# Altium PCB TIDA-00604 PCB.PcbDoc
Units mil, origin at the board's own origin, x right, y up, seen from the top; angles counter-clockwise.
Board outline 3890 x 2960 mil, 4 copper layers (Top Layer, Top, Mid-Layer 1, ly2, Mid-Layer 2, ly3, Bottom Layer, Bottom), stack 18.2 mil thick; 80 components, 35 nets, 214 pads, 61 vias.
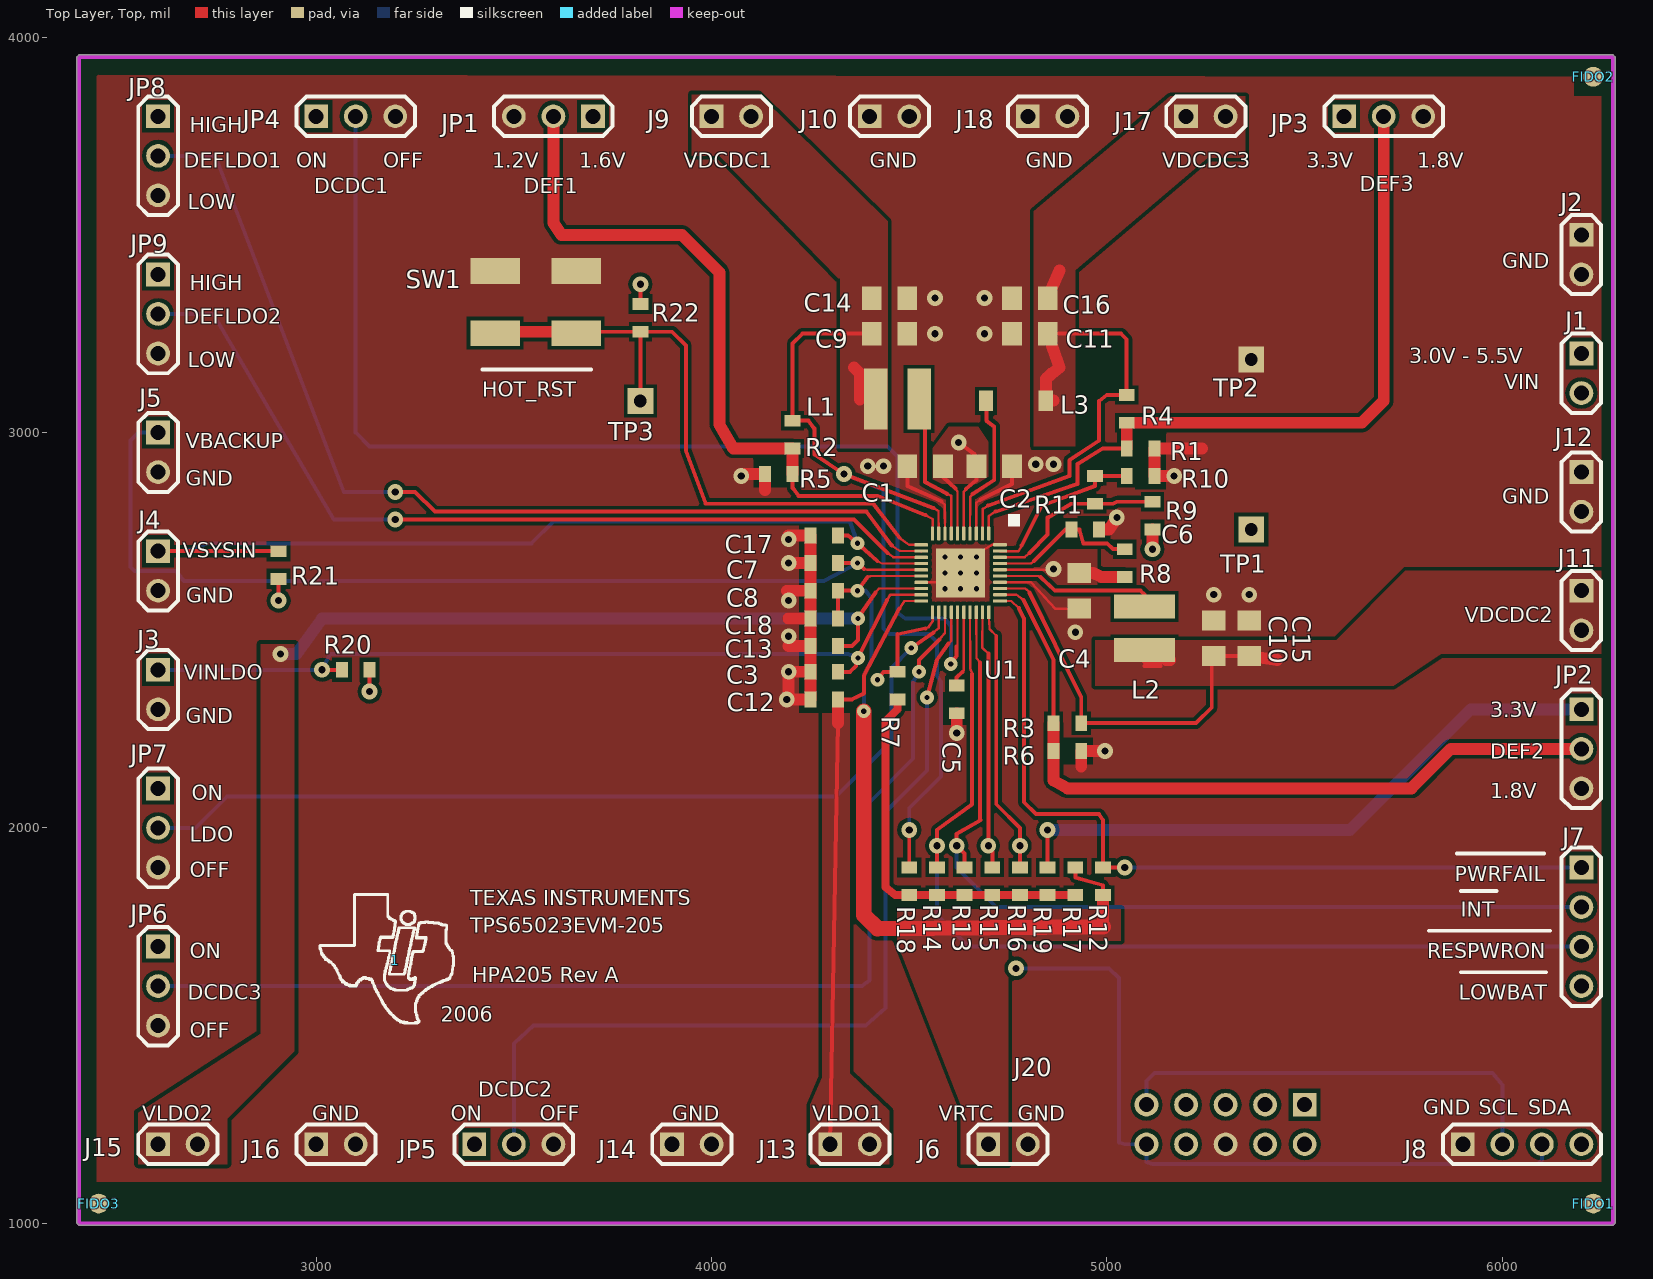
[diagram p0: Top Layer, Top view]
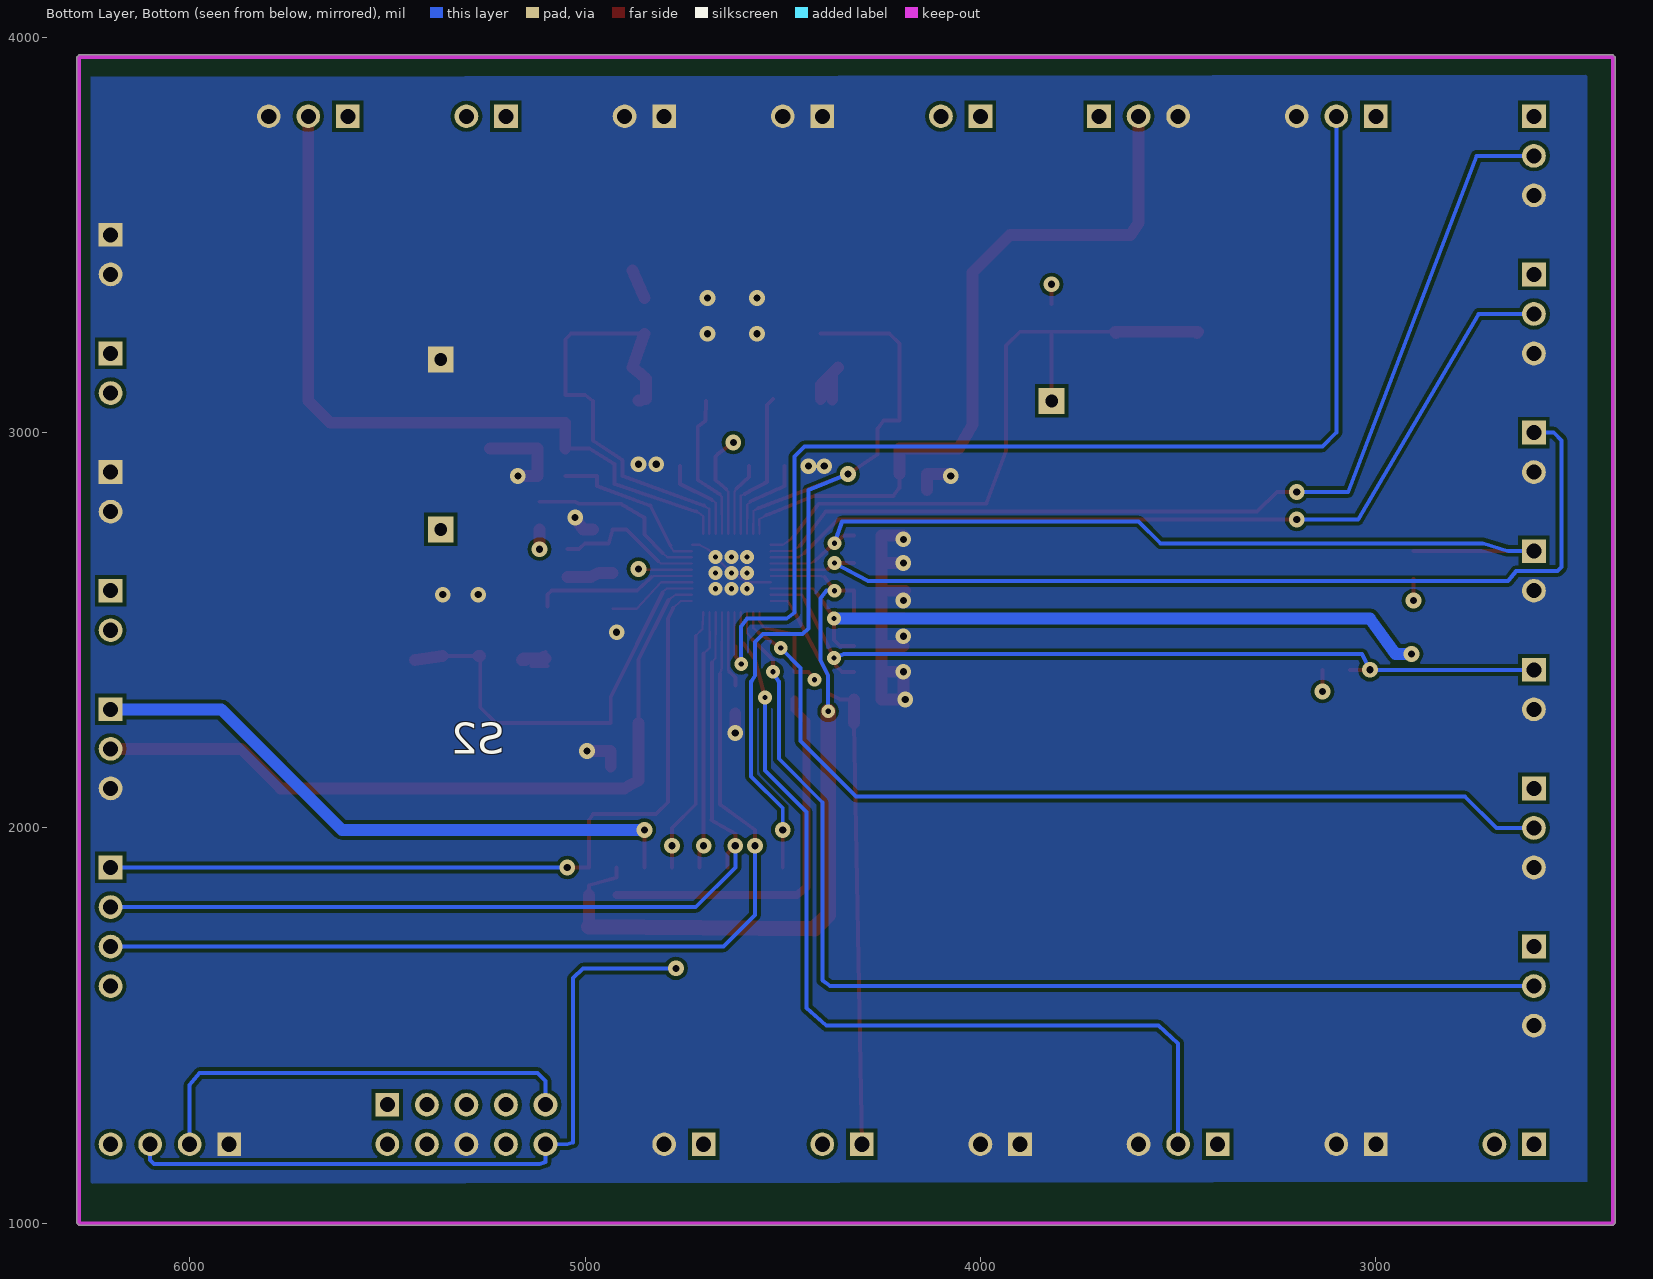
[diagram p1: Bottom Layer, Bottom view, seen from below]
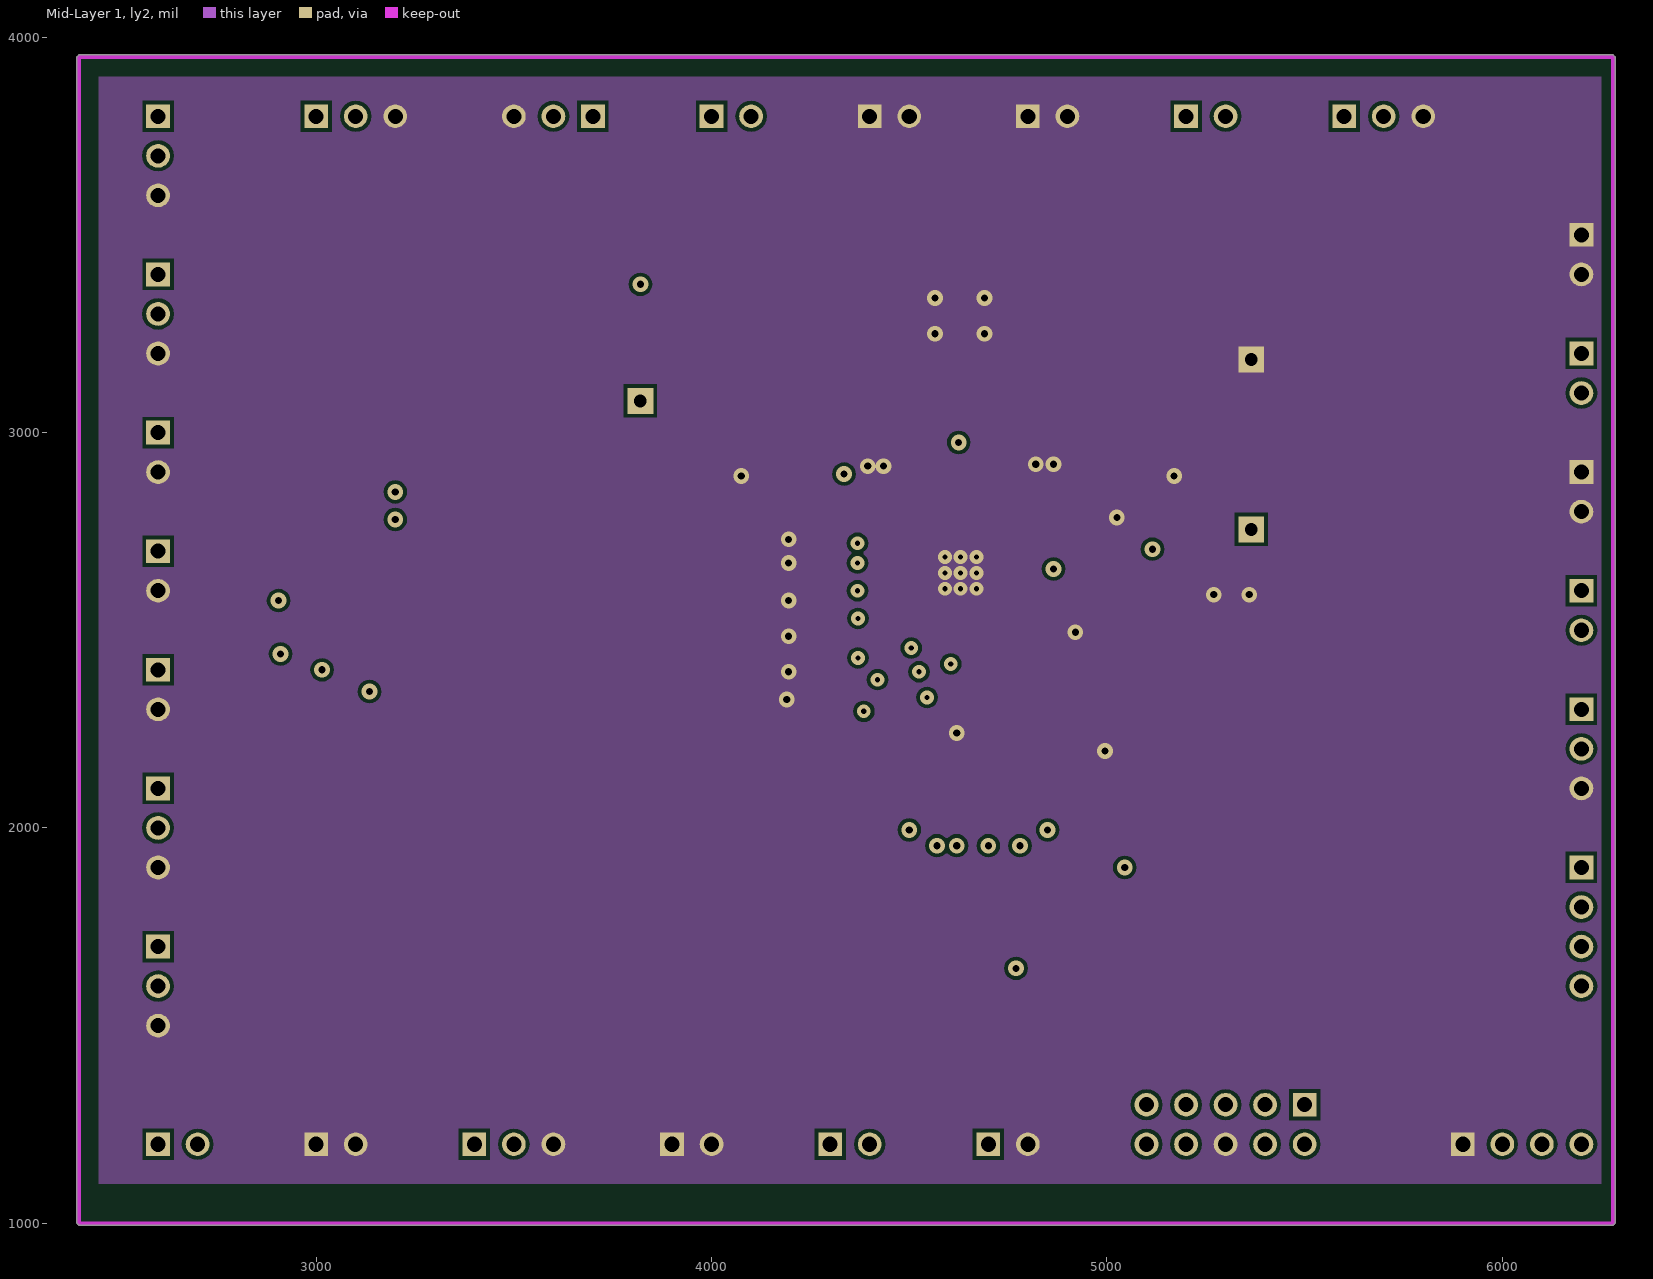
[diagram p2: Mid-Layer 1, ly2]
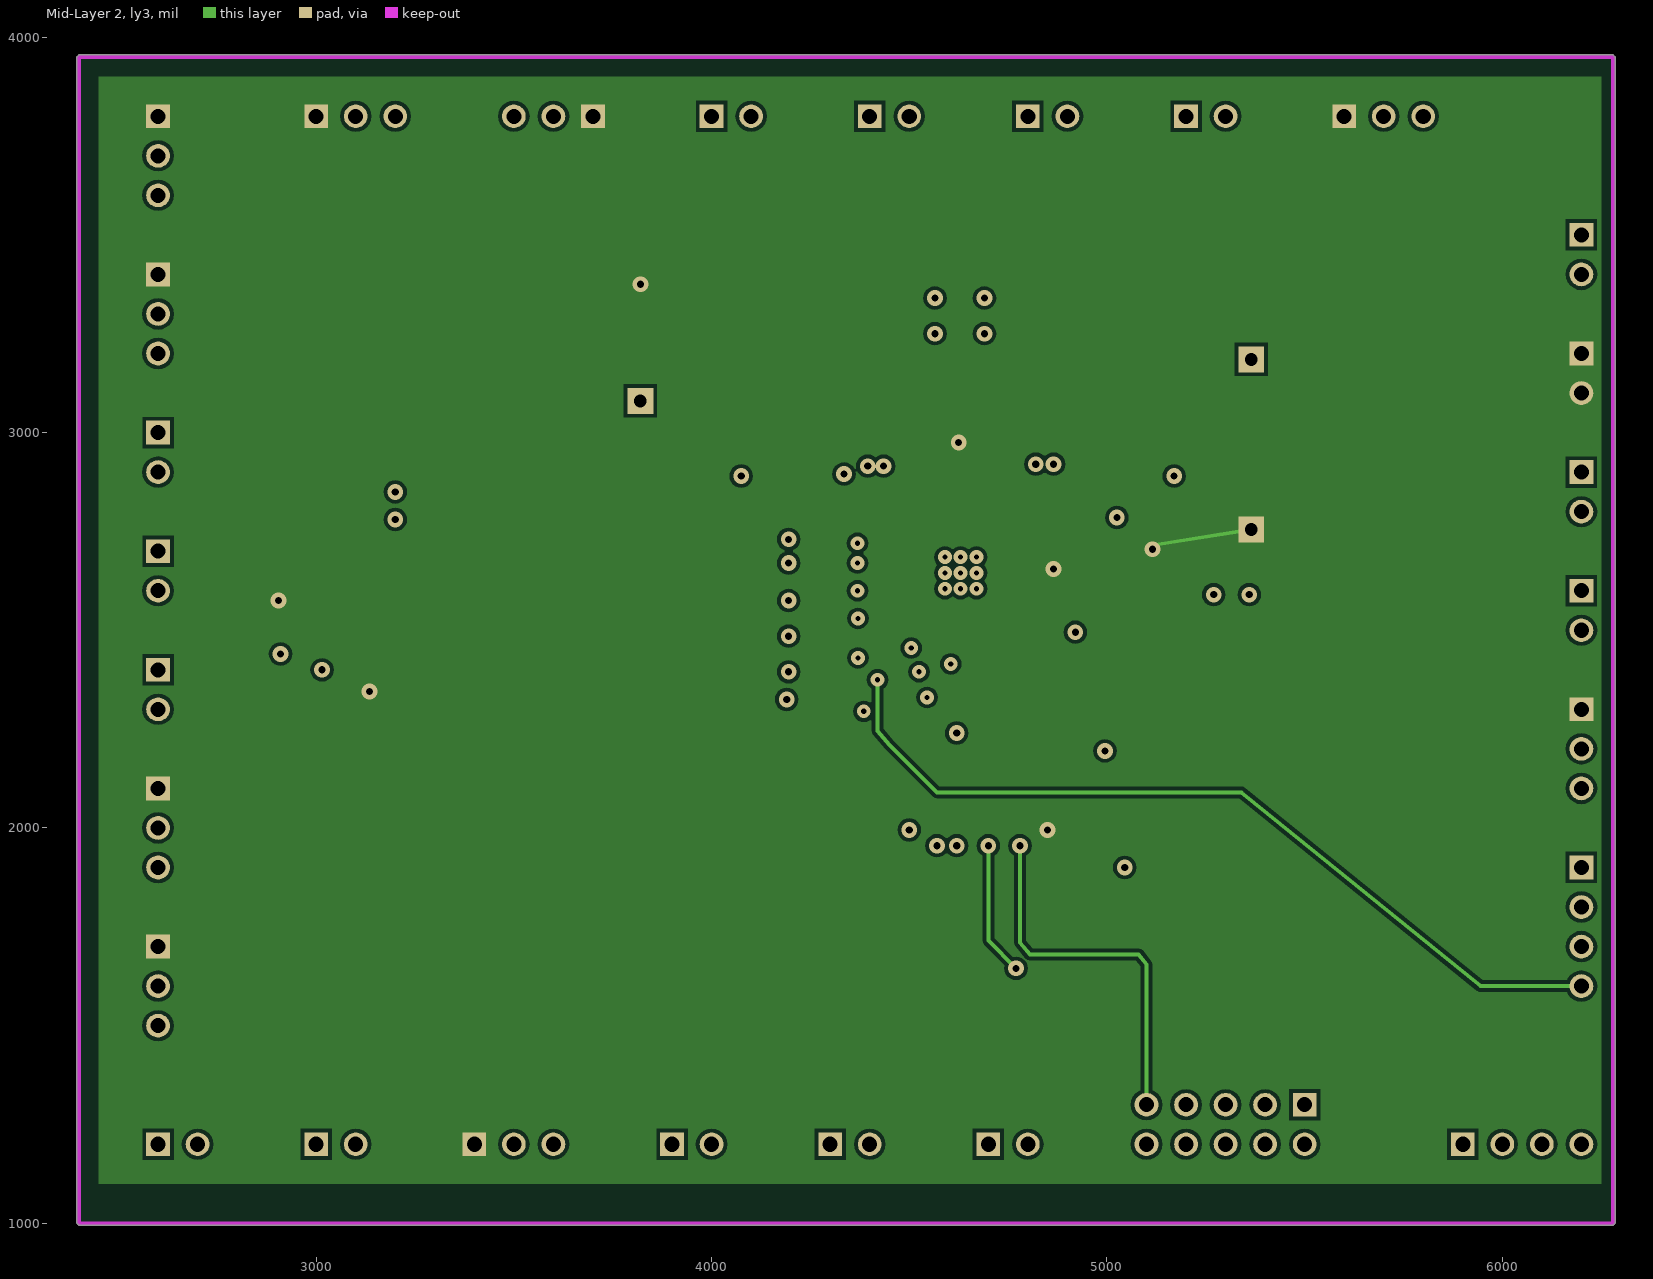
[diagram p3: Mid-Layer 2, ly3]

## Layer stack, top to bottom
Top Solder, Top Mask: solder mask 0.4, Solder Resist, Dk 3.5
Top Layer, Top: signal copper 1.4
Dielectric 1: dielectric 12.6, FR-4, Dk 4.8
Mid-Layer 1, ly2: signal copper 1.4
Mid-Layer 2, ly3: signal copper 1.4
Bottom Layer, Bottom: signal copper 1.4
Bottom Solder, Bot Mask: solder mask 0.4, Solder Resist, Dk 3.5

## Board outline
2395,1000 2400,995 6280,995 6285,1000 6285,3950 6280,3955 2400,3955 2395,3950

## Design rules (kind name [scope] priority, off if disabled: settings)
Clearance "Clearance_Top Layer, Top" [ExistsOnLayer('Top Layer, Top') vs ExistsOnLayer('Top Layer, Top')] p1: gap=10 except(15: THPad-Via)
Clearance "Clearance_Mid-Layer 1, ly2" [ExistsOnLayer('Mid-Layer 1, ly2') vs ExistsOnLayer('Mid-Layer 1, ly2')] p2: gap=9.2 except(10: Arc-Arc Track-THPad Track-Track Arc-Track THPad-THPad Arc-THPad)
Clearance "Clearance_Mid-Layer 2, ly3" [ExistsOnLayer('Mid-Layer 2, ly3') vs ExistsOnLayer('Mid-Layer 2, ly3')] p3: gap=9.2 except(10: Arc-Arc Track-THPad Track-Track Arc-Track THPad-THPad Arc-THPad)
Clearance "Clearance_Bottom Layer, Bottom" [ExistsOnLayer('Bottom Layer, Bottom') vs ExistsOnLayer('Bottom Layer, Bottom')] p4: gap=9.2 except(9.5: Arc-Arc Arc-THPad Arc-Track Track-Track Track-THPad; 9.7: THPad-THPad; 15: THPad-Via)
Clearance [All] p5: gap=10 except(7.8: THPad-THPad; 8.6: Track-THPad Arc-THPad; 9.2: Arc-Arc Track-Track Arc-Track)
PlaneClearance [All] p1: clearance=10
PolygonConnect PolygonConnect_22 [IsPolygon And InNet('VIN') And OnLayer('Mid-Layer 2, ly3') vs IsVia] p1: connectstyle=Direct reliefconductorwidth=15 reliefentries=4 polygonreliefangle="90 Angle" airgapwidth=10
PolygonConnect PolygonConnect_21 [IsPolygon And InNet('VIN') And OnLayer('Mid-Layer 2, ly3') vs IsPad] p2: connectstyle=Direct reliefconductorwidth=15 reliefentries=4 polygonreliefangle="90 Angle" airgapwidth=10
PolygonConnect PolygonConnect_20 [IsPolygon And InNet('GND') And OnLayer('Mid-Layer 1, ly2') vs IsVia] p3: connectstyle=Direct reliefconductorwidth=15 reliefentries=4 polygonreliefangle="90 Angle" airgapwidth=10
PolygonConnect PolygonConnect_19 [IsPolygon And InNet('GND') And OnLayer('Mid-Layer 1, ly2') vs IsPad] p4: connectstyle=Direct reliefconductorwidth=15 reliefentries=4 polygonreliefangle="90 Angle" airgapwidth=10
PolygonConnect PolygonConnect_18 [IsPolygon And InNet('GND') And OnLayer('Bottom Layer, Bottom') vs IsVia] p5: connectstyle=Direct reliefconductorwidth=15 reliefentries=4 polygonreliefangle="90 Angle" airgapwidth=10
PolygonConnect PolygonConnect_17 [IsPolygon And InNet('GND') And OnLayer('Bottom Layer, Bottom') vs IsPad] p6: connectstyle=Direct reliefconductorwidth=15 reliefentries=4 polygonreliefangle="90 Angle" airgapwidth=10
PolygonConnect PolygonConnect_16 [IsPolygon And InNet('GND') And OnLayer('Top Layer, Top') vs IsVia] p7: connectstyle=Direct reliefconductorwidth=15 reliefentries=4 polygonreliefangle="90 Angle" airgapwidth=10
PolygonConnect PolygonConnect_15 [IsPolygon And InNet('GND') And OnLayer('Top Layer, Top') vs IsPad] p8: connectstyle=Direct reliefconductorwidth=15 reliefentries=4 polygonreliefangle="90 Angle" airgapwidth=10
PolygonConnect PolygonConnect_14 [IsPolygon And InNet('VLD02') And OnLayer('Top Layer, Top') vs IsVia] p9: connectstyle=Direct reliefconductorwidth=15 reliefentries=4 polygonreliefangle="90 Angle" airgapwidth=10
PolygonConnect PolygonConnect_13 [IsPolygon And InNet('VLD02') And OnLayer('Top Layer, Top') vs IsPad] p10: connectstyle=Direct reliefconductorwidth=15 reliefentries=4 polygonreliefangle="90 Angle" airgapwidth=10
PolygonConnect PolygonConnect_12 [IsPolygon And InNet('VRTC') And OnLayer('Top Layer, Top') vs IsVia] p11: connectstyle=Direct reliefconductorwidth=15 reliefentries=4 polygonreliefangle="90 Angle" airgapwidth=10
PolygonConnect PolygonConnect_11 [IsPolygon And InNet('VRTC') And OnLayer('Top Layer, Top') vs IsPad] p12: connectstyle=Direct reliefconductorwidth=15 reliefentries=4 polygonreliefangle="90 Angle" airgapwidth=10
PolygonConnect PolygonConnect_10 [IsPolygon And InNet('VDCDC2') And OnLayer('Top Layer, Top') vs IsVia] p13: connectstyle=Direct reliefconductorwidth=15 reliefentries=4 polygonreliefangle="90 Angle" airgapwidth=10
PolygonConnect PolygonConnect_9 [IsPolygon And InNet('VDCDC2') And OnLayer('Top Layer, Top') vs IsPad] p14: connectstyle=Direct reliefconductorwidth=15 reliefentries=4 polygonreliefangle="90 Angle" airgapwidth=10
PolygonConnect PolygonConnect_8 [IsPolygon And InNet('VLD01') And OnLayer('Top Layer, Top') vs IsVia] p15: connectstyle=Direct reliefconductorwidth=15 reliefentries=4 polygonreliefangle="90 Angle" airgapwidth=10
PolygonConnect PolygonConnect_7 [IsPolygon And InNet('VLD01') And OnLayer('Top Layer, Top') vs IsPad] p16: connectstyle=Direct reliefconductorwidth=15 reliefentries=4 polygonreliefangle="90 Angle" airgapwidth=10
PolygonConnect PolygonConnect_6 [IsPolygon And InNet('VDCDC3') And OnLayer('Top Layer, Top') vs IsVia] p17: connectstyle=Direct reliefconductorwidth=15 reliefentries=4 polygonreliefangle="90 Angle" airgapwidth=10
PolygonConnect PolygonConnect_5 [IsPolygon And InNet('VDCDC3') And OnLayer('Top Layer, Top') vs IsPad] p18: connectstyle=Direct reliefconductorwidth=15 reliefentries=4 polygonreliefangle="90 Angle" airgapwidth=10
PolygonConnect PolygonConnect_4 [IsPolygon And InNet('VIN') And OnLayer('Top Layer, Top') vs IsVia] p19: connectstyle=Direct reliefconductorwidth=15 reliefentries=4 polygonreliefangle="90 Angle" airgapwidth=10
PolygonConnect PolygonConnect_3 [IsPolygon And InNet('VIN') And OnLayer('Top Layer, Top') vs IsPad] p20: connectstyle=Direct reliefconductorwidth=15 reliefentries=4 polygonreliefangle="90 Angle" airgapwidth=10
PolygonConnect PolygonConnect_2 [IsPolygon And InNet('VDCDC1') And OnLayer('Top Layer, Top') vs IsVia] p21: connectstyle=Direct reliefconductorwidth=15 reliefentries=4 polygonreliefangle="90 Angle" airgapwidth=10
PolygonConnect PolygonConnect_1 [IsPolygon And InNet('VDCDC1') And OnLayer('Top Layer, Top') vs IsPad] p22: connectstyle=Direct reliefconductorwidth=15 reliefentries=4 polygonreliefangle="90 Angle" airgapwidth=10
PolygonConnect [All] p23: connectstyle=Relief reliefconductorwidth=10 reliefentries=4 polygonreliefangle="90 Angle" airgapwidth=10
RoutingVias [All] p1: holewidth=28 width=50 viastyle="Through Hole" minholewidth=28 minwidth=50 maxholewidth=28 maxwidth=50
SolderMaskExpansion [All] p1: expansion=4
UnpouredPolygon [All] p1: allowunpoured=FALSE
Width [All] p1: maxlimit=10 minlimit=10 preferedwidth=10
28 further rules are at their usual default settings.

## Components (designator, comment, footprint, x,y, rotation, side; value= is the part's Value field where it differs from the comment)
1 "" TIBUG3 3200,1665 r0 top
C1 "10uF" C0805 4540,2915 r0 top
C2 "10uF" C0805 4715,2915 r180 top
C3 "1.0uF" C603 4285,2395 r0 top
C4 "10uF" C0805 4930,2600 r90 top
C5 "1500pF" C603 4620,2325 r90 top
C6 "1.0uF" C603 4945,2755 r180 top
C7 "1.0uF" C603 4285,2670 r180 top
C8 "2.2uF" C603 4285,2600 r180 top
C9 "10uF" C0805 4450,3250 r180 top
C10 "10uF" C0805 5270,2480 r270 top
C11 "10uF" C0805 4805,3250 r0 top
C12 "2.2uF" C603 4285,2325 r180 top
C13 "2.2uF" C603 4285,2460 r180 top
C14 "10uF" C0805 4450,3340 r180 top
C15 "10uF" C0805 5360,2480 r270 top
C16 "10uF" C0805 4805,3340 r0 top
C17 "1.0uF" C603 4285,2740 r0 top
C18 "2.2uF" C603 4285,2530 r180 top
FIDO1 "" TOP_FIDO 6230,1050 r0 top
FIDO2 "" TOP_FIDO 6230,3900 r0 top
FIDO3 "" TOP_FIDO 2450,1050 r0 top
J1 "PTC36SAAN" HDR100_1X2 6200,3200 r270 top
J2 "PTC36SAAN" HDR100_1X2 6200,3500 r270 top
J3 "PTC36SAAN" HDR100_1X2 2600,2400 r270 top
J4 "PTC36SAAN" HDR100_1X2 2600,2700 r270 top
J5 "PTC36SAAN" HDR100_1X2 2600,3000 r270 top
J6 "PTC36SAAN" HDR100_1X2 4700,1200 r0 top
J7 "" HDR100_1X4 6200,1900 r270 top
J8 "PTC36SAAN" HDR100_1X4 5900,1200 r0 top
J9 "PTC36SAAN" HDR100_1X2 4000,3800 r0 top
J10 "PTC36SAAN" HDR100_1X2 4400,3800 r0 top
J11 "PTC36SAAN" HDR100_1X2 6200,2600 r270 top
J12 "PTC36SAAN" HDR100_1X2 6200,2900 r270 top
J13 "PTC36SAAN" HDR100_1X2 4300,1200 r0 top
J14 "PTC36SAAN" HDR100_1X2 3900,1200 r0 top
J15 "PTC36SAAN" HDR100_1X2 2600,1200 r0 top
J16 "PTC36SAAN" HDR100_1X2 3000,1200 r0 top
J17 "PTC36SAAN" HDR100_1X2 5200,3800 r0 top
J18 "PTC36SAAN" HDR100_1X2 4800,3800 r0 top
J20 "2510-6002UB" CONN_2510-6002UB 5500,1300 r180 top
JP1 "" HDR100_1X3 3700,3800 r180 top
JP2 "" HDR100_1X3 6200,2300 r270 top
JP3 "" HDR100_1X3 5600,3800 r0 top
JP4 "" HDR100_1X3 3000,3800 r0 top
JP5 "" HDR100_1X3 3400,1200 r0 top
JP6 "" HDR100_1X3 2600,1700 r270 top
JP7 "" HDR100_1X3 2600,2100 r270 top
JP8 "" HDR100_1X3 2600,3800 r270 top
JP9 "" HDR100_1X3 2600,3400 r270 top
L1 "2.2uH" IND_VLCF4020 4470,3085 r180 top
L2 "2.2uH" IND_VLCF4020 5095,2505 r270 top
L3 "2.2uH" IND_VLF4012A 4770,3080 r0 top
R1 "Open" R603 5085,2960 r180 top
R2 "Open" R603 4205,2995 r270 top
R3 "Open" R603 4900,2265 r180 top
R4 "Open" R603 5050,3060 r270 top
R5 "Open" R603 4170,2895 r180 top
R6 "Open" R603 4900,2195 r0 top
R7 "100k" R603 4470,2360 r270 top
R8 "10" R603 5045,2670 r90 top
R9 "1.20M" R603 5115,2790 r90 top
R10 "499k" R603 5085,2890 r180 top
R11 "100k" R603 4970,2855 r90 top
R12 "100k" R603 4990,1865 r90 top
R13 "100k" R603 4640,1865 r90 top
R14 "100k" R603 4570,1865 r90 top
R15 "4.75k" R603 4710,1865 r270 top
R16 "4.75k" R603 4780,1865 r270 top
R17 "Open" R603 4920,1865 r270 top
R18 "Open" R603 4500,1865 r270 top
R19 "0" R603 4850,1865 r270 top
R20 "0" R603 3100,2400 r180 top
R21 "Open" R603 2905,2665 r90 top
R22 "100k" R603 3820,3290 r270 top
SW1 "KT11P2JM" SWITCH_KT11X 3555,3330 r180 top
TP1 "" TP-032 5365,2755 r0 top
TP2 "" TP-032 5365,3185 r0 top
TP3 "STD" TP-032 3820,3080 r0 top
U1 "" QFP-40[RSB] 4630,2645 r180 top

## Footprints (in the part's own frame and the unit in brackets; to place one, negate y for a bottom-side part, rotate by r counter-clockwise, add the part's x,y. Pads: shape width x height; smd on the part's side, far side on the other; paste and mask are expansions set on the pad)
C603 [mil]
  rect 30x40 smd: 1(-35,0) 2(35,0)
C0805 [mil]
  rect 50x60 smd: 1(-45,0) 2(45,0)
CONN_2510-6002UB [mil]
  rect 60x60 hole 38: 1(0,0)
  round 60 hole 38: 2(0,100) 3(100,0) 4(100,100) 5(200,0) 6(200,100) 7(300,0) 8(300,100) 9(400,0) 10(400,100)
HDR100_1X2 [mil]
  rect 60x60 hole 38: 1(0,0)
  round 60 hole 38: 2(100,0)
  silkscreen extent -50,-50 150,50
HDR100_1X3 [mil]
  rect 60x60 hole 38: 1(0,0)
  round 60 hole 38: 2(100,0) 3(200,0)
  silkscreen extent -50,-50 250,50
HDR100_1X4 [mil]
  rect 60x60 hole 38: 1(0,0)
  round 60 hole 38: 2(100,0) 3(200,0) 4(300,0)
  silkscreen extent -50,-50 350,50
IND_VLCF4020 [mil]
  rect 60x154 smd: 1(-55,0) 2(55,0)
IND_VLF4012A [mil]
  rect 36x52 smd: 1(-76,0) 2(75,0)
QFP-40[RSB] [mil]
  rrect50% 8x35 smd mask-1000: 1(-71.1,-99.5) 2(-55.3,-99.5) 3(-39.5,-99.5) 4(-23.7,-99.5) 5(-7.9,-99.5) 6(7.9,-99.5) 7(23.7,-99.5) 8(39.5,-99.5) 9(55.3,-99.5) 10(71.1,-99.5) 21(71.1,99.5) 22(55.3,99.5) 23(39.5,99.5) 24(23.7,99.5) 25(7.9,99.5) 26(-7.9,99.5) 27(-23.7,99.5) 28(-39.5,99.5) 29(-55.3,99.5) 30(-71.1,99.5)
  rrect50% 35x8 smd mask-1000: 11(99.5,-71.1) 12(99.5,-55.3) 13(99.5,-39.5) 14(99.5,-23.7) 15(99.5,-7.9) 16(99.5,7.9) 17(99.5,23.7) 18(99.5,39.5) 19(99.5,55.3) 20(99.5,71.1) 31(-99.5,71.1) 32(-99.5,55.3) 33(-99.5,39.5) 34(-99.5,23.7) 35(-99.5,7.9) 36(-99.5,-7.9) 37(-99.5,-23.7) 38(-99.5,-39.5) 39(-99.5,-55.3) 40(-99.5,-71.1)
  rect 124x124 smd: 41(0,0)
  silkscreen extent -150,-148 -120,-118
R603 [mil]
  rect 30x40 smd: 1(-35,0) 2(35,0)
SWITCH_KT11X [mil]
  rect 125x65 smd: 1(-102.5,78.6) 2(-102.5,-78.4) 3(102.5,-78.4) 4(102.5,78.6)
TIBUG3 [mil]
  silkscreen extent -190,-159 147,167
TOP_FIDO [mil]
  round 50 smd mask-1000: 1(0,0)
  Top Layer, Top pour cut-out: -50,-50 50,-50 50,50 -50,50
TP-032 [mil]
  rect 65x65 hole 32: 1(0,0)

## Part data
1: "Pattern, TI Bug 0.3\" High"
C1 C2 C4 C8 C9 C10 C11 C14 C15 C16 C18: "Capacitor, Ceramic, 6.3V, X5R, 10%"
C3 C6 C7 C12 C13 C17: "Capacitor, Ceramic, 6.3V, X5R,10%"
C5: "Capacitor, Ceramic, 50V, X7R, 10%"
J1 J2 J3 J4 J5 J6 J9 J10 J11 J12 J13 J14 J15 J16 J17 J18: "Header, 2 pin, 100mil spacing, (36-pin strip)"
J7 J8: "Header, 4 pin, 100mil spacing, (36-pin strip)"
J20: "Connector, Male Straight 2x5 pin, 100mil spacing, 4 Wall"
JP1 JP2 JP3 JP4 JP5 JP6 JP7 JP8 JP9: "Header, 3 pin, 100mil spacing, (36-pin strip)"
L1 L2: "Inductor, SMT, 1.72A, 59milliohm"
L3: "Inductor, SMT, 1.5A, 87milliohm"
R1 R2 R3 R4 R5 R6 R7 R8 R10 R11 R12 R13 R14 R15 R16 R17 R18 R19 R20 R21 R22: "Resistor, Chip, 1/16W, 1%"
R9: "Resistor, Chip, 1.20M-Ohms, 1/16-W, 1%"
SW1: "Switch, SPST, PB Momentary, Sealed Washable"
TP1 TP2 TP3: "Test Point, O.032 Hole"
U1: "IC, Power Management IC for Li-Ion Powered Systems"

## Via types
v1: diameter 40, hole 18, Top Layer, Top to Bottom Layer, Bottom, 41 vias
v2: diameter 35, hole 13, Top Layer, Top to Bottom Layer, Bottom, 20 vias

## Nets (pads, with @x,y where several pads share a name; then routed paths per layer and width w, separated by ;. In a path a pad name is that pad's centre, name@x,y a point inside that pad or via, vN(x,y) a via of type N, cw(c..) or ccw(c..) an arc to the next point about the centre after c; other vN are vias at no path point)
DCDC1_EN: JP4.2 U1.25 | length 2970.7
  Top Layer, Top w6: 4620,2459 4622,2465 U1.25
  Top Layer, Top w10: v2(4605,2415) 4620,2435 4620,2459
  Bottom Layer, Bottom w10: JP4.2 3100,3000 3135,2965 4445,2965 4470,2940 4470,2545 4490,2530 4590,2530 4605,2510 v2(4605,2415)
DCDC2_EN: JP5.2 U1.24 | length 2288.9
  Top Layer, Top w6: 4599,2466 4601,2468 4606,2473 U1.24
  Top Layer, Top w10: v2(4545,2330) 4570,2425 4599,2466
  Bottom Layer, Bottom w10: JP5.2 3500,1455 3550,1500 4390,1500 4440,1545 4440,2040 4545,2145 v2(4545,2330)
DCDC3_EN: JP6.2 U1.23 | length 2811.7
  Top Layer, Top w6: 4577,2477 4590.5,2493 U1.23
  Top Layer, Top w10: v2(4525,2395) 4525,2425 4577,2477
  Bottom Layer, Bottom w10: JP6.2 4380,1600 4400,1615 4400,2065 4510,2175 4510,2370 v2(4525,2395)
DEFDCDC1: JP1.2 R2.2 R5.1 U1.10 | length 1862.5
  Top Layer, Top w6: 4541,2791 4559,2781 U1.10
  Top Layer, Top w10: R5.1 4205,2860 4220,2840 4420,2840 4541,2791
  Top Layer, Top w30: JP1.2 3600,3530 3620,3500 3925,3500 4020,3405 4020,3020 4055,2960 R2.2 R5.1
DEFDCDC2: JP2.2 R3.2 R6.1 U1.32 | length 1920.5
  Top Layer, Top w6: U1.32 4771,2590 4789,2577 4789,2576
  Top Layer, Top w10: 4789,2576 4865,2425 R3.2
  Top Layer, Top w30: R3.2 R6.1 4865,2120 4900,2100 5770,2100 5870,2200 JP2.2
DEFDCDC3: JP3.2 R1.2 R4.2 U1.1 | length 1929.4
  Top Layer, Top w6: U1.1 4701,2789 4719,2801 4718.5,2800
  Top Layer, Top w10: 4718.5,2800 4925,2870 4925,2920 4990,2960 R1.2
  Top Layer, Top w30: R1.2 R4.2 5645,3025 5700,3080 JP3.2
DEFLDO1: JP8.2 U1.12 | length 2583.3
  Top Layer, Top w6: 4456,2714 4476,2701 U1.12
  Top Layer, Top w10: v1(3200,2850) 3250,2850 3300,2800 4392,2800 4456,2714
  Bottom Layer, Bottom w10: JP8.2 2745,3700 3070,2850 v1(3200,2850)
DEFLDO2: JP9.2 U1.13 | length 2266.8
  Top Layer, Top w6: 4445,2695 4459,2685 U1.13
  Top Layer, Top w10: v1(3200,2780) 4360,2780 4445,2695
  Bottom Layer, Bottom w10: JP9.2 2740,3300 3045,2780 v1(3200,2780)
GND: C1.1 C2.1 C3.1 C4.1 C5.1 C6.1 C7.2 C8.2 C9.1 C10.1 C11.1 C12.2 C13.2 C14.1 C15.1 C16.1 C17.1 C18.2 J2.1 J2.2 J3.2 J4.2 J5.2 J6.2 J8.1 J10.1 J10.2 J12.1 J12.2 J14.1 J14.2 J16.1 J16.2 J18.1 J18.2 J20.6 JP1.3 JP2.3 JP3.3 JP4.3 JP5.3 JP6.3 JP7.3 JP8.3 JP9.3 R1.1 R5.2 R6.2 R10.1 SW1.2 SW1.3 TP2.1 U1.3 U1.8 U1.17 U1.34 U1.40 U1.41 | length 2720.1
  Top Layer, Top w6: U1.17 4588,2621 v2(4630,2645) 4669,2684 4669,2685 4688,2704 4710,2716 U1.40 ; 4580,2826 4590,2818 U1.8 ; U1.3 4669.5,2823 4680,2830 ; U1.34 4729.2,2621.3 4729.5,2621.5 4808,2621.5 4870,2554 4930,2554 C4.1
  Top Layer, Top w10: C1.1 4495,2910 4495,2865 4581,2826 ; v2(4590,2645) 4600,2645 v2(4630,2645) ; 4679.5,2830 4760,2870 4760,2910 C2.1
  Top Layer, Top w30: v1(4075,2890) 4080,2890 4085,2895 R5.2 4135,2855 ; 4190,2600 C8.2 ; 4195,2460 C13.2 ; 4195,2530 C18.2 ; v1(4195,2670) C7.2 ; v1(4195,2730) 4195,2740 C17.1 C7.2 ; v1(4620,2240) C5.1 ; 4935,2155 R6.2 4990,2195 v1(4995,2195) ; C6.1 5005,2755 v1(5025,2785) ; v1(5170,2890) 5169.67,2890 R10.1 R1.1 5240,2959.67 ; v1@4190,2395 v1(4195,2395) ; v1@4190,2395 v1(4195,2395) ; v1@4190,2395 v1(4195,2395) ; v1@4190,2395 v1(4195,2395) ; v1@4190,2395 v1(4195,2395) ; v1@4190,2395 v1(4195,2395) ; v1@4190,2395 v1(4195,2395) ; v1@4190,2395 v1(4195,2395) ; v1@4190,2395 v1(4195,2395) ; v1@4190,2395 v1(4195,2395) ; v1@4190,2395 v1(4195,2395) ; v1@4190,2395 v1(4195,2395) ; v1@4190,2395 v1(4195,2395) ; v1@4190,2395 v1(4195,2395) ; v1@4190,2395 v1(4195,2395) ; v1@4190,2395 v1(4195,2395) ; v1@4190,2395 v1(4195,2395) ; v1@4190,2395 v1(4195,2395) ; v1@4190,2395 v1(4195,2395) ; v1@4190,2395 v1(4195,2395) ; v1@4190,2395 v1(4195,2395) ; v1@4190,2395 v1(4195,2395) ; v1@4190,2395 v1(4195,2395) ; v1@4190,2395 v1(4195,2395) ; v1@4190,2395 v1(4195,2395) ; v1@4190,2395 v1(4195,2395) ; v1@4190,2395 v1(4195,2395) ; v1@4190,2395 v1(4195,2395) ; v1@4190,2395 v1(4195,2395) ; v1@4190,2395 v1(4195,2395) ; v1@4190,2395 v1(4195,2395) ; v1@4190,2395 v1(4195,2395) ; v1@4190,2395 v1(4195,2395) ; v1@4190,2395 v1(4195,2395) ; v1@4190,2395 v1(4195,2395) ; v1@4190,2395 v1(4195,2395) ; v1@4190,2395 v1(4195,2395) ; v1@4190,2395 v1(4195,2395) ; v1@4190,2395 v1(4195,2395) ; v1@4190,2395 v1(4195,2395) ; v1@4190,2395 v1(4195,2395) ; v1@4190,2395 v1(4195,2395) ; v1@4190,2395 v1(4195,2395) ; v1@4190,2395 v1(4195,2395) ; v1@4190,2395 v1(4195,2395) ; v1@4190,2395 v1(4195,2395) ; v1@4190,2395 v1(4195,2395) ; v1@4190,2395 v1(4195,2395) ; v1@4190,2395 v1(4195,2395) ; v1@4190,2395 v1(4195,2395) ; v1@4190,2395 v1(4195,2395) ; v1@4190,2395 v1(4195,2395) ; v1@4190,2395 v1(4195,2395) ; v1@4190,2395 v1(4195,2395) ; v1@4190,2395 v1(4195,2395) ; v1@4190,2395 v1(4195,2395) ; v1@4190,2395 v1(4195,2395) ; v1@4190,2395 v1(4195,2395) ; v1@4190,2395 v1(4195,2395) ; v1@4190,2395 v1(4195,2395) ; v1@4190,2395 v1(4195,2395) ; v1@4190,2395 v1(4195,2395) ; v1@4190,2395 v1(4195,2395) ; v1@4190,2395 v1(4195,2395) ; v1(4195,2395) 4195,2325 C12.2 C3.1 ; v1(4195,2395) C3.1 ; C3.1 C13.2 ; C13.2 C18.2 ; C18.2 C8.2 ; C8.2 4250,2605 4250,2665 C7.2
  other v1: 4190,2325 4195,2485 4920,2495 4195,2575 5270,2590 5360,2590 4395,2915 4435,2915 4820,2920 4865,2920 4565,3250 4690,3250 4565,3340 4690,3340
  other v2: 4590,2605 4630,2605 4670,2605 4670,2645 4590,2685 4630,2685 4670,2685
L1: L1.1 U1.7 | length 386.4
  Top Layer, Top w6: 4596,2845 4606,2840 U1.7
  Top Layer, Top w10: L1.1 4540,3070 4540,2875 4596,2845
L2: L2.1 U1.35 | length 414.2
  Top Layer, Top w6: U1.35 4827,2637 4832,2635
  Top Layer, Top w10: 4832,2635 4868,2600 5085,2600 5095,2590 L2.1
L3: L3.1 U1.4 | length 379.9
  Top Layer, Top w6: U1.4 4654,2837 4661,2844 4659.5,2844.5
  Top Layer, Top w10: 4659.5,2844.5 4715,2880 4715,3015 4695,3030 L3.1
LDO_EN: JP7.2 U1.22 | length 2328
  Top Layer, Top w6: 4561,2494 4575,2506 U1.22
  Top Layer, Top w10: v2(4505,2455) 4561,2494
  Bottom Layer, Bottom w10: JP7.2 2695,2000 2775,2080 4315,2080 4455,2220 4455,2405 v2(4505,2455)
LOWBAT_SNS: R10.2 R11.2 U1.39 | length 424.9
  Top Layer, Top w6: U1.39 4776,2700 4784,2713 4784,2714
  Top Layer, Top w10: 4784,2714 4835,2815 4970,2865 R11.2 R10.2
PWRFAIL_SNS: R9.2 R11.1 U1.38 | length 462.5
  Top Layer, Top w6: U1.38 4792,2685 4804,2695
  Top Layer, Top w10: 4804,2695 4850,2742 4850,2785 4910,2820 4960,2820 R11.1 4985,2820 5015,2820 5025,2825 R9.2
SCLK: J8.2 J20.9 R16.1 U1.30 | length 2755.8
  Top Layer, Top w6: U1.30 4703,2503 4720,2486
  Top Layer, Top w10: 4720,2486 4720,2060 4780,2000 v1(4780,1955) R16.1
  Mid-Layer 2, ly3 w10: v1(4780,1955) 4780,1710 4805,1680 5080,1680 5100,1655 J20.9
  Bottom Layer, Bottom w10: J20.9 5100,1360 5120,1380 5975,1380 6000,1350 J8.2
SDAT: J8.3 J20.10 R15.1 U1.29 | length 2841.3
  Top Layer, Top w6: U1.29 4685,2455 4700,2441
  Top Layer, Top w10: 4700,2441 v1(4700,1955) 4700,1950 4710,1940 R15.1
  Mid-Layer 2, ly3 w10: v1(4700,1955) 4700,1715 v1(4770,1645)
  Bottom Layer, Bottom w10: v1(4770,1645) 5005,1645 5030,1620 5030,1205 5045,1200 J20.10 5100,1155 5115,1150 6090,1150 6100,1160 J8.3
TRESPWRON: C5.2 U1.26 | length 192.7
  Top Layer, Top w6: 4635,2395 4638,2399 U1.26
  Top Layer, Top w10: C5.2 4620,2380 4635,2395
VBACKUP: C7.1 J5.1 U1.15 | length 2481.7
  Top Layer, Top w6: 4385,2655 4393,2653 U1.15
  Top Layer, Top w10: C7.1 v2(4369,2670) 4370,2670 4385,2655
  Bottom Layer, Bottom w10: J5.1 2550,3000 2530,2980 2530,2660 2540,2650 2645,2650 2665,2625 4285,2625 v2(4369,2670)
VCC: C6.2 R8.2 U1.37 | length 383.5
  Top Layer, Top w6: U1.37 4808,2669 4814,2674 4815,2675
  Top Layer, Top w10: 4815,2675 4895,2755 C6.2 4930,2755 4940,2720 5000,2720 5015,2705 R8.2
VDCDC1: C9.2 C14.2 J9.1 J9.2 L1.2 R2.1 R18.1 U1.9 | length 2317.3
  Top Layer, Top w6: 4561,2809 4562,2809 4574,2801 U1.9
  Top Layer, Top w10: C9.2 4230,3250 4205,3225 R2.1 4245,3030 4260,3010 4260,2945 v1(4335,2895) 4360,2885 4561,2809 ; R18.1 v1(4500,1995)
  Top Layer, Top w30: 4360,3165 4375,3150 ; 4374.8,3083.5 4374.8,3088.5 4375,3150 ; L1.2@4404,3085 4404,3121 4375,3150
  Bottom Layer, Bottom w10: v1(4335,2895) 4435,2855 4435,2505 4450,2490 4550,2490 4570,2470 4570,2385 4580,2370 4580,2130 4500,2050 v1(4500,1995)
VDCDC2: C10.2 C15.2 J11.1 J11.2 L2.2 R3.1 U1.33 | length 1255.4
  Top Layer, Top w6: 4804,2596 4804,2597 4793.5,2605.5 U1.33 ; U1.33 4729,2605.5 U1.33
  Top Layer, Top w10: 4804,2596 4935,2330 R3.1 5225,2265 5265,2305 5265,2434.55 5265,2435 C10.2 C15.2 ; 5096.5,2409.8 5095.2,2409.8 5095,2410 5135,2410 ; L2.2@5100,2445 5140,2429 L2.2@5150,2425
  Top Layer, Top w30: L2.2@5100,2429 5140,2429 5156,2429 5160,2425 L2.2@5150,2425 ; C10.2@5265,2434.55 C10.2 ; C15.2 5430,2425
VDCDC3: C11.2 C16.2 J17.1 J17.2 L3.2 R4.1 U1.2 | length 1311.5
  Top Layer, Top w6: U1.2 4685.3,2744.2 4685.5,2744 4685.5,2807 4700,2815 4699,2815
  Top Layer, Top w10: 4699,2815 4905,2890 4905,2930 4980,2980 4980,3080 5000,3095 R4.1 5050,3235 5035,3250 C11.2
  Top Layer, Top w30: C11.2 4880,3165 4860.01,3147.95 ; 4860,3150 4860.01,3147.95 ; 4865.2,3081.5 4860.2,3081.5 4846,3085 4846,3136 4860.01,3147.95 ; C16.2 4880,3410 C16.2
VIN: C1.2 C2.2 C4.2 J1.1 J1.2 JP1.1 JP2.1 JP3.1 JP4.1 JP5.1 JP6.1 JP7.1 JP8.1 JP9.1 R8.1 R9.1 R19.1 R20.1 R21.1 R22.1 TP1.1 U1.5 U1.6 U1.36 | length 2752.2
  Top Layer, Top w6: 4617,2858 4622,2851 U1.6 ; U1.5 4638,2851 4643,2857 ; U1.36 4865,2653 v1(4865,2655)
  Top Layer, Top w10: v1(2905,2575) R21.1 ; v1(3135,2345) R20.1 ; R22.1 v1(3820,3375) ; C1.2 4585,2888 4617,2858 ; v1(4625,2975) 4665,2945 4670,2940 C2.2 4670,2880 4643,2857 ; R19.1 v1(4850,1995)
  Top Layer, Top w30: C4.2 4965,2645 4985,2635 R8.1 ; v1(5115,2705) R9.1
  Mid-Layer 2, ly3 w10: v1(5115,2705) 5115,2715 TP1.1
  Bottom Layer, Bottom w30: v1(4850,1995) 5615,1995 5920,2300 JP2.1
VINLDO: C3.2 J3.1 R20.2 U1.19 | length 2176.8
  Top Layer, Top w6: 4444,2576 4452,2590 U1.19
  Top Layer, Top w10: v1(3015,2400) R20.2 ; C3.2 4350,2395 4365,2410 v2(4370,2430) 4444,2576
  Bottom Layer, Bottom w10: J3.1 2715,2400 v1(3015,2400) 3035,2440 3975,2440 4010,2440 4345,2440 v2(4370,2430)
VLD01: C12.1 J13.1 J13.2 U1.20 | length 1496.6
  Top Layer, Top w6: 4475,2555 4488,2574 U1.20
  Top Layer, Top w10: J13.1 4320,2265 ; C12.1 4355,2325 4385,2340 4385,2385 4475,2555
  Top Layer, Top w30: 4320,2265 C12.1
VLD02: C13.1 J15.1 J15.2 U1.18 | length 1816.7
  Top Layer, Top w6: 4415,2596 4423,2605 U1.18
  Top Layer, Top w10: C13.1 4355,2460 4370,2475 v2(4370,2530) 4415,2596
  Bottom Layer, Bottom w30: v1(2910,2440) 2950,2440 3015,2530 v2(4370,2530)
VPULLUP: R7.2 R13.1 R14.1 R15.2 R16.2 R17.2 R18.2 R19.2 | length 974.4
  Top Layer, Top w20: R7.2 4470,2300 4440,2270 4440,1850 4465,1830 R18.2 R14.1 R13.1 R15.2 R16.2 R19.2 R17.2
VRTC: C8.1 C18.1 J6.1 R12.1 R17.1 U1.16 | length 1971.5
  Top Layer, Top w6: 4395,2635 4401,2637 U1.16
  Top Layer, Top w10: C18.1 C8.1 v2(4369,2600) 4395,2635 ; R17.1 4920,1875 4990,1855 R12.1
  Top Layer, Top w30: 4990,1750 R12.1
  Top Layer, Top w40: v2(4385,2295) 4385,1780 4420,1745 4990,1750
  Bottom Layer, Bottom w10: v2(4369,2600) 4390,2600 4405,2580 4405,2425 4385,2385 v2(4385,2295)
VSYSIN: C17.2 J4.1 R21.2 U1.14 | length 2375.4
  Top Layer, Top w6: 4419,2675 4431,2669 U1.14
  Top Layer, Top w10: J4.1 R21.2 ; C17.2 4345,2740 v2(4369,2720) 4419,2675
  Bottom Layer, Bottom w10: J4.1 2665,2700 2730,2720 3545,2720 3600,2775 4350,2775 v2(4369,2720)
~HOT_RST: R22.2 SW1.1 SW1.4 TP3.1 U1.11 | length 1854.9
  Top Layer, Top w6: 4475,2734 4500,2716 U1.11
  Top Layer, Top w10: SW1.1 3655,3250 SW1.1@3675,3255 ; SW1.1@3660,3255 SW1.1@3675,3255 ; TP3.1 R22.2 ; 4475,2734 4409,2820 3985,2820 3935,2955 3935,3220 3900,3255 R22.2 ; SW1.1@3675,3255 R22.2 ; SW1.1@3675,3255 R22.2
  Top Layer, Top w30: SW1.4 3452.5,3252.5 3450,3255 3660,3255 3657.5,3252.5 SW1.1
~INT: J7.2 R13.2 U1.28 | length 2369.1
  Top Layer, Top w6: U1.28 4670,2429 4679,2419
  Top Layer, Top w10: R13.2 4640,1935 v1(4620,1955) 4620,1985 4680,2020 4679,2020 4679,2419
  Bottom Layer, Bottom w10: v1(4620,1955) 4620,1900 4720,1800 J7.2
~LOWBAT: J7.4 R7.1 U1.21 | length 2428.1
  Top Layer, Top w6: 4541,2505 4540,2505 4548,2507 4559,2523 U1.21
  Top Layer, Top w10: v2(4420,2375) 4435,2395 R7.1 4470,2490 4541,2505
  Mid-Layer 2, ly3 w10: v2(4420,2375) 4420,2245 4450,2210 4570,2090 5340,2090 5945,1600 J7.4
~PWRFAIL: J7.1 R12.2 U1.31 | length 2100.1
  Top Layer, Top w6: U1.31 4758,2574 4777,2556 4777,2556.5
  Top Layer, Top w10: 4777,2556.5 4790,2530 4790,2065 4820,2035 4980,2035 4990,2020 R12.2 4995,1900 v1(5045,1900)
  Bottom Layer, Bottom w10: v1(5045,1900) 5090,1900 J7.1
~RESPWRON: J7.3 R14.2 U1.27 | length 2529.7
  Top Layer, Top w6: U1.27 4654,2403 4659,2389
  Top Layer, Top w10: R14.2 v1(4570,1955) 4570,1995 4659,2060 4659,2389
  Bottom Layer, Bottom w10: v1(4570,1955) 4570,1780 4650,1700 J7.3
pads on no net: FIDO1.1 FIDO2.1 FIDO3.1 J8.4 J20.1 J20.2 J20.3 J20.4 J20.5 J20.7 J20.8

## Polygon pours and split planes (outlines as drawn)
VDCDC1 on Top Layer, Top "Top Layer, Top-VDCDC1" (solid, remove dead copper, pour order 2): 4325,3390 4325,2960 4445,2960 4445,3390
VIN on Top Layer, Top "Top Layer, Top-VIN" (solid, remove dead copper, pour order 4): 4710,2870 4710,2960 4675,3015 4600,3015 4560,2960 4560,2870
VDCDC3 on Top Layer, Top "Top Layer, Top-VDCDC3" (solid, remove dead copper, pour order 6): 4815,3200 4815,2965 4920,2965 4920,3200
VLD01 on Top Layer, Top "Top Layer, Top-VLD01" (solid, remove dead copper, pour order 8): 4250,1150 4450,1150 4450,1285 4350,1380 4350,2290 4280,2290 4280,1370 4250,1300
VDCDC2 on Top Layer, Top "Top Layer, Top-VDCDC2" (solid, remove dead copper, pour order 10): 4970,2475 4970,2360 5205,2360 5205,2475
VDCDC1 on Top Layer, Top "Top Layer, Top-VDCDC1 1" (solid, remove dead copper, pour order 12): 3950,3855 3950,3700 4020,3700 4320,3390 4445,3390 4445,3535 4120,3855
VIN on Top Layer, Top "Top Layer, Top-VIN 1" (solid, remove dead copper, pour order 14): 4975,2605 4975,2705 4875,2705 4830,2660 4730,2660 4730,2650 4830,2650 4875,2605
VRTC on Top Layer, Top "Top Layer, Top-VRTC" (solid, remove dead copper, pour order 16): 4750,1150 4750,1715 5035,1715 5035,1795 4470,1795 4470,1710 4630,1300 4630,1150
VDCDC3 on Top Layer, Top "Top Layer, Top-VDCDC3 1" (solid, remove dead copper, pour order 18): 5160,3850 4815,3560 4815,3195 4920,3195 4920,3410 5255,3695 5350,3695 5350,3850
VLD02 on Top Layer, Top "Top Layer, Top-VLD02" (solid, remove dead copper, pour order 20): 2775,1150 2775,1265 2945,1435 2945,2465 2860,2465 2860,1480 2550,1280 2550,1150
VDCDC2 on Top Layer, Top "Top Layer, Top-VDCDC2 1" (solid, remove dead copper, pour order 22): 6250,2650 5755,2650 5580,2475 5205,2475 5205,2360 5725,2360 5845,2440 6250,2440
GND on Top Layer, Top "Top Layer, Top-GND" (solid, remove dead copper, pour order 24): 2445,3905 2445,1105 6250,1105 6250,3900
GND on Bottom Layer, Bottom "Bottom Layer, Bottom-GND" (solid, remove dead copper, pour order 26): 2465,3905 2465,1105 6250,1100 6250,3900
GND on Mid-Layer 1, ly2 "Mid-Layer 1, ly2-GND" (solid, remove dead copper, pour order 28): 2450,3900 2450,1100 6250,1100 6250,3900
VIN on Mid-Layer 2, ly3 "Mid-Layer 2, ly3-VIN" (solid, remove dead copper, pour order 30): 2450,3900 2450,1100 6250,1100 6250,3900

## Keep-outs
Keep-Out Layer, Board:
  lines w10: 2400,1000 2400,3950 6280,3950 6280,1000 2400,1000

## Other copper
Top Layer, Top:
  pour cut-out: 4105,2930 4105,2860 4190,2860 4190,2930
  pour cut-out: 4585,2345 4585,2260 4655,2260 4655,2345
  pour cut-out: 4880,2230 4880,2160 4965,2160 4965,2230
  pour cut-out: 4925,2790 4925,2720 5010,2720 5010,2790
  pour cut-out: 4220,2290 4305,2290 4305,2765 4220,2765
  pour cut-out: 4435,2380 4435,2295 4505,2295 4505,2380
  pour cut-out: 5070,2855 5150,2855 5150,2995 5070,2995

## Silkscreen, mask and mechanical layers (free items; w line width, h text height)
Top Overlay, Top Silk:
  lines w10: 3420,3160 3695,3160 ; 5815,1740 6120,1740 ; 5885,1935 6105,1935 ; 5895,1635 6110,1635 ; 5895,1840 5985,1840
  text "HIGH" at 2680,3760 h37.5
  text "DEFLDO1" at 2665,3670 h37.5
  text "ON" at 2950,3670 h37.5
  text "OFF" at 3170,3670 h37.5
  text "1.2V" at 3445,3670 h37.5
  text "1.6V" at 3665,3670 h37.5
  text "VDCDC1" at 3930,3670 h37.5
  text "GND" at 4400,3670 h37.5
  text "GND" at 4795,3670 h37.5
  text "VDCDC3" at 5140,3670 h37.5
  text "3.3V" at 5505,3670 h37.5
  text "1.8V" at 5785,3670 h37.5
  text "DEF3" at 5640,3610 h37.5
  text "DCDC1" at 2995,3605 h37.5
  text "DEF1" at 3525,3605 h37.5
  text "LOW" at 2675,3565 h37.5
  text "GND" at 6000,3415 h37.5
  text "HIGH" at 2680,3360 h37.5
  text "DEFLDO2" at 2665,3275 h37.5
  text "3.0V - 5.5V" at 5765,3175 h37.5
  text "LOW" at 2675,3165 h37.5
  text "VIN" at 6005,3110 h37.5
  text "HOT_RST" at 3420,3090 h37.5
  text "VBACKUP" at 2670,2960 h37.5
  text "GND" at 2670,2865 h37.5
  text "GND" at 6000,2820 h37.5
  text "VSYSIN" at 2663,2683 h37.5
  text "GND" at 2672,2570 h37.5
  text "VDCDC2" at 5905,2520 h37.5
  text "VINLDO" at 2665,2375 h37.5
  text "3.3V" at 5970,2280 h37.5
  text "GND" at 2670,2265 h37.5
  text "DEF2" at 5970,2175 h37.5
  text "1.8V" at 5970,2075 h37.5
  text "ON" at 2685,2070 h37.5
  text "LDO" at 2680,1965 h37.5
  text "OFF" at 2680,1875 h37.5
  text "PWRFAIL" at 5880,1865 h37.5
  text "TEXAS INSTRUMENTS" at 3390,1805 h37.5
  text "INT" at 5895,1775 h37.5
  text "TPS65023EVM-205" at 3390,1735 h37.5
  text "ON" at 2680,1670 h37.5
  text "RESPWRON" at 5810,1670 h37.5
  text "HPA205 Rev A" at 3395,1610 h37.5
  text "DCDC3" at 2675,1565 h37.5
  text "LOWBAT" at 5890,1565 h37.5
  text "2006" at 3315,1510 h37.5
  text "OFF" at 2680,1470 h37.5
  text "DCDC2" at 3410,1320 h37.5
  text "GND" at 5800,1275 h37.5
  text "SCL" at 5940,1275 h37.5
  text "SDA" at 6065,1275 h37.5
  text "VLDO2" at 2560,1260 h37.5
  text "GND" at 2990,1260 h37.5
  text "ON" at 3340,1260 h37.5
  text "OFF" at 3565,1260 h37.5
  text "GND" at 3900,1260 h37.5
  text "VLDO1" at 4255,1260 h37.5
  text "VRTC" at 4575,1260 h37.5
  text "GND" at 4775,1260 h37.5
Bottom Overlay, Bot Silk:
  text "S2" at 5202.81,2187.58 h78.12
Top Paste, Top Paste:
  text "P1" at 5950.86,2182.58 h78.12
Mechanical 3, FAB:
  drawing of 126 lines, arcs and shapes, not listed
  text "FABRICATION CHART" at 3342.5,9635 h125
  text "NOTES: UNLESS OTHERWISE SPECIFIED" at 8025,9565 h125
  text "FINISHED" at 5774.69,9383.75 h93.75
  text "FINISHED" at 2024.69,9318.75 h93.75
  text "1." at 8025,9317.58 h78.12
  text "MATERIAL:" at 8200,9317.58 h78.12
  text "ALL MATERIALS,  INCLUDING BUT NOT LIMITED TO BASE LAMINATE,  BONDING MATERIALS" at 9575,9317.58 h78.12
  text "SILKSCREEN" at 3107.5,9218.75 h93.75
  text "SOLDERMASK" at 4372.34,9218.75 h93.75
  text "COPPER" at 5805.16,9218.75 h93.75
  text "AND SOLDERMASK COATINGS FORMING THE FINISHED PRINTED CIRCUIT BOARD SHALL MEET" at 9575,9142.58 h78.12
  text "THICKNESS" at 1952.03,9118.75 h93.75
  text "WEIGHT" at 5840.31,9053.75 h93.75
  text "UL-796 REQUIREMENTS AND BE RoHS COMPLIANT AND HAVE A FLAMMABILITY OF UL94V-0." at 9575,8972.58 h78.12
  text "0.031" at 2165,8887.58 h78.12
  text "LAYER 1" at 3365,8887.58 h78.12
  text "LAYER 1" at 4665,8887.58 h78.12
  text "1 OZ." at 5915,8887.58 h78.12
  text "2." at 8025,8742.58 h78.12
  text "BASE LAMINATE:" at 8200,8742.58 h78.12
  text "PLASTIC SHEET, LAMINATED METAL CLAD, TWO SIDES, BASE MATERIAL NEMA TYPE FR-4" at 9575,8742.58 h78.12
  text "0.062" at 2165,8687.58 h78.12
  text "LAYER 2" at 3365,8687.58 h78.12
  text "LAYER 2" at 4665,8687.58 h78.12
  text "2 OZ." at 5915,8687.58 h78.12
  text "GLASS EPOXY RESIN, COPPER-CLAD IN ACCORDANCE WITH 2 LAYER STACK-UP," at 9525,8610 h78.12
  text "0.093" at 2165,8487.58 h78.12
  text "NONE" at 3365,8487.58 h78.12
  text "NONE" at 4665,8487.58 h78.12
  text "OTHER" at 5915,8487.58 h78.12
  text "COMPLIANT WITH LEAD FREE PROCESS." at 9525,8439.69 h78.12
  text "0.125" at 2165,8287.58 h78.12
  text "3." at 8025,8242.58 h78.12
  text "SOLDERMASK:" at 8200,8242.58 h78.12
  text "SOLDERMASK OVER BARE COPPER (SMOBC) USING LIQUID PHOTO-IMAGEABLE SOLDERMASK IN" at 9575,8242.58 h78.12
  text "ACCORDANCE WITH IPC-SM-840." at 9575,8067.58 h78.12
  text "DESIGN" at 2037.97,7968.75 h93.75
  text "TRACE/GAP SPACING" at 3300.47,7968.75 h93.75
  text "LAYER COUNT" at 5408.28,7968.75 h93.75
  text "4." at 8025,7842.58 h78.12
  text "PLATING:" at 8200,7842.58 h78.12
  text "HOLES REQUIRING PLATING, SEE HOLE CHART, TO HAVE 1 OZ. (0.0014) MIN. THK MIN." at 9575,7842.58 h78.12
  text "SMD" at 2115,7737.58 h78.12
  text "0.010/0.010" at 3665,7737.58 h78.12
  text "SINGLE SIDED" at 5515,7737.58 h78.12
  text "THICK COPPER." at 9575,7667.58 h78.12
  text "THRU-HOLE" at 2115,7537.58 h78.12
  text "0.008/0.007" at 3665,7537.58 h78.12
  text "2 LAYER" at 5515,7537.58 h78.12
  text "PLATE WITH RoHS COMPLIANT, IMMERSION SILVER PREFERRED, IMMERSION TIN OR Sn/Ag/Cu," at 9575,7450 h78.12
  text "5." at 8025,7417.58 h78.12
  text "FINISH:" at 8200,7417.58 h78.12
  text "MIX" at 2115,7337.58 h78.12
  text "0.006/0.006" at 3665,7337.58 h78.12
  text "4 LAYER" at 5515,7337.58 h78.12
  text "WITH RMA FLUX, 0.0005\" +/- 0.0003\" THICK MIN ALL EXPOSED AREAS" at 9575,7279.69 h78.12
  text "OTHER" at 5515,7137.58 h78.12
  text "AS COATED, NO ACTIVE FLUXES ARE ACCEPTABLE." at 9575,7122.58 h78.12
  text "6." at 8025,6892.58 h78.12
  text "LEGEND:" at 8200,6892.58 h78.12
  text "IF REQUIRED, SILKSCREEN LEGEND(S) WITH WHITE NON-CONDUCTIVE EPOXY INK." at 9575,6892.58 h78.12
  text "7." at 8025,6642.58 h78.12
  text "MARKINGS:" at 8200,6642.58 h78.12
  text "BOARD MUST BEAR VENDOR'S IDENTIFICATION CODE (ETCH OR WHITE NON-CONDUCTIVE INK)." at 9575,6642.58 h78.12
  text "LOCATION OPTIONAL." at 9575,6492.58 h78.12
  text "8." at 8025,6272.58 h78.12
  text "WORKMANSHIP:" at 8200,6267.58 h78.12
  text "BOARD IS TO BE MANUFACTURED PER IPC-A-600 CLASS 2 REQUIREMENTS OR BETTER." at 9575,6267.58 h78.12
  text "DOCUMENTATION:" at 8200,6022.58 h78.12
  text "9." at 8025,6017.58 h78.12
  text "PCB VENDOR IS REQUIRED TO RETURN ANY AND ALL DOCUMENTS SUPPLIED OR ULTIMATELY PURCHASED BY TEXAS" at 9575,6017.58 h78.12
  text "INSTRUMENTS UPON COMPLETION OF PURCHASE ORDER." at 9575,5842.58 h78.12
  text "10." at 7950,5617.58 h78.12
  text "DRILL SIZES:" at 8200,5617.58 h78.12
  text "HOLE DIAMETERS SHOWN ARE FINISHED SIZES AFTER PLATING UNLESS OTHERWISE NOTED." at 9575,5607.81 h78.12
  text "11." at 7950,5392.58 h78.12
  text "PANEL BORDER:" at 8200,5392.58 h78.12
  text "ANY METAL IN BORDER AREA INCLUDING PART NUMBER, DATECODE AND/OR REVISION LETTERS" at 9575,5392.58 h78.12
  text "MUST BE COVERED WITH SOLDERMASK." at 9575,5217.58 h78.12
  text "PROCESS CHANGES:" at 8200,4997.58 h78.12
  text "12." at 7950,4992.58 h78.12
  text "NO DIMENSIONAL, MATERIAL, OR PROCESS CHANGES ARE ALLOWED WITHOUT PRIOR EXPLICIT WRITTEN PERMISSION" at 9575,4992.58 h78.12
  text "FROM TEXAS INSTRUMENTS." at 9575,4817.58 h78.12
  text "TEXAS INSTRUMENTS" at 12845,2668.75 h93.75
  text "Board No." at 12720,2536.25 h31.25
  text "Rev." at 13995,2536.25 h31.25
  text "HPA205" at 12990,2393.75 h93.75
  text "A" at 14200,2368.75 h93.75
  text "Date:" at 12695,2286.25 h31.25
  text "Filename:" at 13295,2286.25 h31.25
  text "11/10/06" at 12945,2243.5 h37.5

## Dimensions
2340,1000 to 2340,3950 on Mechanical 3, FAB
2400,1000 to 6280,3950 on Mechanical 3, FAB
